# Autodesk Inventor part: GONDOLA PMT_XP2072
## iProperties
Shininess: 64.0
Length Units: 11272
Angle Units: 11279
Time Units: 11290
Mass Units: 11286
Length Display Precision: 3
Angle Display Precision: 2
Compacted: True
Part Number: GONDOLA PMT_XP2072
Document SubType Name: Modeling
Created: 2004-08
Designer: John Blackburn
Manufacturer: Standard
Standards Organization: Custom
Material: Lexan, Clear
Density: 0.0
Volumn: 0.0
Area: 0.0
PropertySet Name: Model Information
Control State: 0
Master: False
Checked Out: False
Author: John Blackburn
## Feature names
1. Base1
